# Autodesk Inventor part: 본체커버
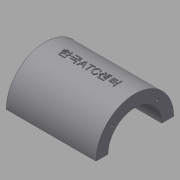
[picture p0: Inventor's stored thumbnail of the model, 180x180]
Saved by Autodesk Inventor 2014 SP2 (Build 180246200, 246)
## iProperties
Created: 2015-12
Part Number: 본체커버
Material: 일반
Document SubType Name: Modeling
Designer: mduedu
Density: 2.71 g/cm^3
Mass: 199.348 g
Surface Area: 200.806 cm^2
Volume: 73.5601 cm^3
Appearance: 기본값
Author: mduedu
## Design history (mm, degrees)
sketch "스케치1"
  geometry: L1 (45, 40)-(-45, 40); L2 (-45, 40)-(-45, -40); L3 (-45, -40)-(45, -40); L4 (45, -40)-(45, 40); L5 (45, 40)-(-45, -40); L6 (-45, 40)-(45, -40); 1 further point
  constraints: 12 end point, 2 midpoint, 2 parallel, 1 horizontal, 1 perpendicular
  dimensions: "d0" = 90 distance of L2.end L3.end; "d2" = 80 distance of L1.end L2.end
extrude "돌출1" new body sketch "스케치1" distance "d3" = 10; taper "d4" = 0 deg
sketch "스케치2"
  geometry: L1 (0, 40)-(0, -40) reference; C1 r 32.5 at (80, 0); 1 further point
  constraints: 1 centre point
  dimensions: "d5" = 65 diameter of C1; "d6" = 80 distance from line of C1.centre L1
extrude "돌출2" join sketch "스케치2" stored distance "d7" = 75; taper "d8" = 0 deg
sketch "스케치3"
  geometry: L1 (-27.5, -20)-(27.5, -20); L2 (27.5, -20)-(27.5, 20); L3 (27.5, 20)-(-27.5, 20); L4 (-27.5, 20)-(-27.5, -20); L5 (-27.5, -20)-(27.5, 20); L6 (27.5, -20)-(-27.5, 20); 1 further point
  constraints: 12 end point, 2 midpoint, 2 parallel, 1 horizontal, 1 perpendicular
  dimensions: "d9" = 55 distance of L2.end L3.end; "d11" = 40 distance of L1.end L2.end
extrude "돌출3" new body sketch "스케치3" stored distance "d12" = 75; taper "d13" = 0 deg
fillet "모깎기1"
fillet "모깎기2"
feature "결합1"
  node "솔리드2"
fillet "모깎기3" dims "d14" = 10
sketch "스케치4"
  geometry: L1 (-37.5, 47.5)-(37.5, 47.5) reference; L2 (35, 10)-(45, 10) reference; L3 (32.5, 47.5)-(40, 10); L4 (37.5, 47.5)-(37.5, 112.5) reference; L5 (45, 10)-(45, 0) reference; 1 further point
  constraints: 2 end point, 1 midpoint, 1 point on line
  dimensions: "d15" = 5 distance from line of L3.start L4; "d16" = 5 distance from line of L3.end L5
sketch "스케치5"
  geometry: L1 (10, 40)-(10, 30) reference; L2 (10, 35)-(56.569, 22.522); L3 (0, 40)-(10, 40) reference; 2 further points
  constraints: 2 end point, 1 midpoint, 2 other
  dimensions: "d17" = 5 distance from line of L2.start L3; "d18" = 15 deg angle of L2 L3
feature "리브1" dims "d19" = 1, "d20" = 6, "d21" = 0, "d22" = 0, "d23" = 1, "d24" = 1
feature "리브2" dims "d25" = 1, "d26" = 6, "d27" = 0, "d28" = 0, "d29" = 1, "d30" = 1
fillet "모깎기4" dims "d31" = 2
fillet "모깎기5" dims "d32" = 2
fillet "모깎기6" dims "d33" = 2
sketch "스케치6"
  geometry: A1 r 10 centre (-35, 30) between (-35, 40) and (-45, 30) reference; A2 r 10 centre (35, 30) between (45, 30) and (35, 40) reference; A3 r 10 centre (35, -30) between (35, -40) and (45, -30) reference; A4 r 10 centre (-35, -30) between (-45, -30) and (-35, -40) reference; 5 further points
  constraints: 4 coincident
hole "구멍1" sketch "스케치6" at (-35, 30), (35, 30), (35, -30), (-35, -30) diameter "d34" = 7; stored, may be unused: countersink angle "d38" = 90 deg, drill point angle "d40" = 118 deg; dims "d35" = 6, "d36" = 12, "d37" = 3, "d39" = 8
fillet "모깎기7" dims "d41" = 2
hole "구멍2" diameter "d44" = 45; stored, may be unused: countersink angle "d48" = 90 deg, drill point angle "d50" = 118 deg; dims "d42" = 10, "d43" = 10, "d45" = 6, "d46" = 4, "d47" = 2, "d49" = 8
sketch "스케치7" dims "d52" = 26.5
  geometry: L1 (0, 0)-(32.5, 0); L2 (0, 0)-(22.981, 22.981); A1 r 32.5 centre (0, 0) between (32.5, 0) and (22.981, 22.981) reference; 3 further points
  constraints: 4 end point, 2 point on circle, 1 coincident, 1 horizontal, 1 point on line, 3 other
  dimensions: "d51" = 45 deg angle of L2 L1
hole "구멍3" sketch "스케치7" at (18.738, 18.738) diameter "d54" = 2.459; stored, may be unused: countersink angle "d58" = 90 deg, drill point angle "d60" = 118 deg; dims "d55" = 8, "d56" = 4, "d57" = 2, "d59" = 10
sketch "스케치13"
  geometry: L1 (-45, 80)-(105, 80); L2 (105, 80)-(105, -30); L3 (105, -30)-(-45, -30); L4 (-45, -30)-(-45, 80); L5 (0, 0)-(60, 0) reference; C1 r 32.5 at (30, 80) reference; 1 further point
  constraints: 8 end point, 2 parallel, 1 coincident, 1 horizontal, 1 midpoint, 1 perpendicular
  dimensions: "d99" = 30 distance between parallel lines of L3 L5; "d126" = 150 distance between parallel lines of L2 L4
extrude "돌출8" cut sketch "스케치13" stored distance "d97" = 10; taper "d98" = 0 deg
node "작업 평면2"
sketch "스케치14"
  geometry: 2 further points
  constraints: 1 coincident, 1 other
feature "엠보싱1" sketch "스케치14" dims "d102" = 0.5, "d103" = 0
sketch "스케치18"
  geometry: L1 (0, -10)-(0, 0) reference; L2 (75, 0)-(75, -10) reference; L3 (0, -5)-(75, -5); C1 r 1.5 at (13, -5); 1 further point
  constraints: 2 end point, 2 midpoint, 1 centre point, 1 point on line
  dimensions: "d127" = 3 diameter of C1; "d128" = 13 distance from line of L1 C1.centre
extrude "돌출9" cut sketch "스케치18" distance "d129" = 2; taper "d130" = 0 deg
chamfer "모따기2" distance "d131" = 0.5; stored, may be unused: second distance "d132" = 2, angle "d133" = 45 deg
fillet "모깎기12" dims "d134" = 0.1
node "솔리드1"
mirror "대칭1"
mirror "대칭2"
pattern_circular "원형 패턴1" dims angle "d62" = 360 deg
mirror "대칭3"
mirror "대칭5"
mirror "대칭6"
